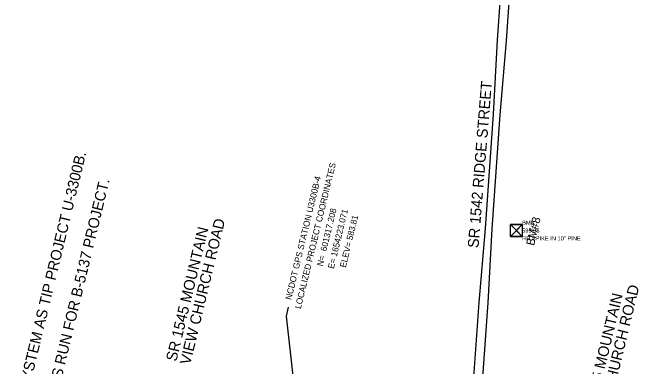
# Model space of a CAD drawing. Extents: x 1649669 to 1659218, y 588594 to 607900.
# Drawn here: x 1652859 to 1655895, y 601392 to 603109 of the extents above; entities that cross this region are included whole.
import ezdxf

# ---------------------------------------------------------------- set-up
doc = ezdxf.new("R2010")
doc.units = 0
for name, color, linetype in [('CTL Bench Mark CELL', 7, 'Continuous'), ('CTL Bench Mark Cogo Comment', 7, 'Continuous'), ('CTL Bench Mark Cogo Elevation', 7, 'Continuous'), ('CTL Bench Mark Cogo Number', 7, 'Continuous'), ('CTL Bench Mark Text', 7, 'Continuous'), ('CTL NGS Horizontal Leader', 7, 'Continuous'), ('CTL NGS Horizontal Text', 7, 'Continuous'), ('CTL Sheet Notes CELL', 7, 'Continuous'), ('Exist Roads EOP', 7, 'Continuous'), ('Sheet Data Field CELL', 7, 'Continuous')]:
    doc.layers.add(name, color=color, linetype=linetype)

msp = doc.modelspace()

# ---------------------------------------------------------------- linework, layer by layer
at = {"layer": 'CTL Bench Mark CELL'}
msp.add_line((1655303, 602051), (1655303, 602051), dxfattribs=at)
msp.add_lwpolyline([(1655274.2, 602079.7), (1655331.7, 602079.7), (1655331.7, 602022.2), (1655274.2, 602022.2)], close=True, dxfattribs=at)
for points in [[(1655331.7, 602079.7), (1655274.2, 602022.2), (1655303, 602050.9), (1655331.7, 602022.2), (1655274.2, 602079.7)], [(1655303, 602050.9), (1655331.7, 602079.7), (1655274.2, 602079.7), (1655303, 602050.9)], [(1655303, 602050.9), (1655274.2, 602022.2), (1655331.7, 602022.2), (1655303, 602050.9)]]:
    msp.add_lwpolyline(points, dxfattribs=at)
at = {"layer": 'CTL NGS Horizontal Leader'}
msp.add_lwpolyline([(1654223.1, 601317.2), (1654187.6, 601636.4), (1654198.1, 601679.9)], dxfattribs=at)
at = {"layer": 'Exist Roads EOP'}
for p, q in [((1655210.9, 602974.5), (1655244.6, 603457.4)), ((1655254.8, 602971.5), (1655288.2, 603449.4)), ((1655191.9, 602615), (1655210.9, 602974.5)), ((1655223.8, 602612.8), (1655254.8, 602971.5)), ((1655153.2, 602061.3), (1655191.9, 602615)), ((1655185.2, 602059.1), (1655223.8, 602612.8)), ((1655122.2, 601702.6), (1655153.2, 602061.3)), ((1655166.1, 601699.6), (1655185.2, 602059.1)), ((1655088.8, 601223.3), (1655122.2, 601702.6)), ((1655132.6, 601219.9), (1655166.1, 601699.6))]:
    msp.add_line(p, q, dxfattribs=at)

# ---------------------------------------------------------------- texts
at = {"layer": 'CTL Bench Mark Cogo Comment'}
msp.add_text('RR SPIKE IN 10" PINE', height=20, dxfattribs=at).set_placement((1655331, 602003))
at = {"layer": 'CTL Bench Mark Cogo Elevation'}
msp.add_text('595.38', height=20, dxfattribs=at).set_placement((1655331, 602041))
at = {"layer": 'CTL Bench Mark Cogo Number'}
msp.add_text('BM8', height=20, dxfattribs=at).set_placement((1655331, 602079))
at = {"layer": 'CTL Bench Mark Text'}
msp.add_text('BM#8', height=40, rotation=76.4261, dxfattribs=at).set_placement((1655388.4, 601975.3))
at = {"layer": 'CTL NGS Horizontal Text'}
for s, p in [('LOCALIZED PROJECT COORDINATES', (1654257.4, 601669.1)), ('NCDOT GPS STATION U3300B-4', (1654211.4, 601712.7)), ('N=  601317.208', (1654363.9, 601875.7)), ('E= 1654223.071', (1654417.5, 601863.5)), ('ELEV= 583.81', (1654475.5, 601869.1))]:
    msp.add_text(s, height=30, rotation=76.4261, dxfattribs=at).set_placement(p)
at = {"layer": 'CTL Sheet Notes CELL'}
for s, p in [('3.    THIS PROJECT USES THE SAME DATUM AND COORDINATE SYSTEM AS TIP PROJECT U-3300B.', (1652431.3, 599171.9)), ('4.    THE ELEVATION OF U3300B-1 WAS REVISED BASED ON LEVELS RUN FOR B-5137 PROJECT.', (1652568.4, 599138.8))]:
    msp.add_text(s, height=52.174, rotation=76.4261, dxfattribs=at).set_placement(p)
at = {"layer": 'Sheet Data Field CELL'}
for s, rotation, p in [('SR 1542 RIDGE STREET', 85.3719, (1655119.2, 601964.8)), ('VIEW CHURCH ROAD', 76.4261, (1653720.8, 601396.8)), ('SR 1545 MOUNTAIN', 76.4261, (1653653.8, 601413)), ('VIEW CHURCH ROAD', 76.4261, (1655729.8, 601075.5)), ('SR 1545 MOUNTAIN', 76.4261, (1655662.9, 601091.6))]:
    msp.add_text(s, height=52.501, rotation=rotation, dxfattribs=at).set_placement(p)

doc.saveas('drawing.dxf')
